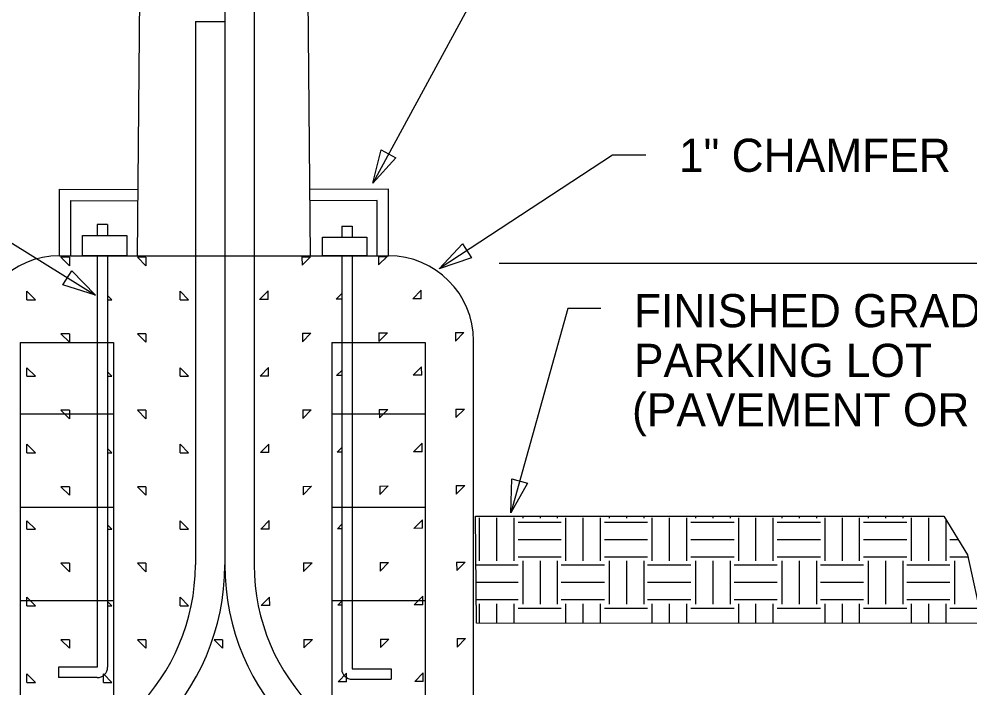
# Model space of a CAD drawing. Extents: x 10117 to 10169, y 10050 to 10161.
# Drawn here: x 10139.75 to 10158.87, y 10084.35 to 10097.81 of the extents above; entities that cross this region are included whole.
import ezdxf

# ---------------------------------------------------------------- set-up
doc = ezdxf.new("R2010")
doc.units = 0
for name, color, linetype in [('G-ANNO-TEXT', 7, 'Continuous'), ('G-DETL-LINE', 7, 'Continuous'), ('G-DETL-OTLN', 7, 'Continuous'), ('G-DETL-PATT', 7, 'Continuous')]:
    doc.layers.add(name, color=color, linetype=linetype)

msp = doc.modelspace()

# ---------------------------------------------------------------- linework, layer by layer
at = {"layer": 'G-ANNO-TEXT'}
for p, q in [((10151.658, 10103.375), (10146.864, 10094.509)), ((10133.842, 10096.882), (10141.285, 10092.251)), ((10151.686, 10095.069), (10148.199, 10092.781)), ((10152.353, 10095.069), (10151.686, 10095.069)), ((10149.402, 10092.896), (10166.935, 10092.896)), ((10150.783, 10091.983), (10149.637, 10087.871)), ((10151.45, 10091.983), (10150.783, 10091.983))]:
    msp.add_line(p, q, dxfattribs=at)
for points in [[(10147.327, 10095.017), (10146.864, 10094.509), (10147.034, 10095.175)], [(10148.848, 10093.007), (10148.199, 10092.781), (10148.665, 10093.286)], [(10140.807, 10092.745), (10141.285, 10092.251), (10140.631, 10092.462)], [(10149.977, 10088.468), (10149.637, 10087.871), (10149.656, 10088.558)]]:
    msp.add_lwpolyline(points, close=True, dxfattribs=at)
at = {"layer": 'G-DETL-LINE'}
for p, q in [((10140.561, 10093.045), (10147.178, 10093.045)), ((10139.772, 10091.302), (10141.65, 10091.302)), ((10139.772, 10091.302), (10139.772, 10082.761)), ((10141.65, 10091.302), (10141.65, 10083.539)), ((10146.039, 10091.302), (10147.916, 10091.302)), ((10146.039, 10091.302), (10146.039, 10083.602)), ((10147.916, 10091.302), (10147.916, 10082.773)), ((10148.889, 10082.719), (10148.889, 10091.334)), ((10139.772, 10089.867), (10141.65, 10089.867)), ((10146.039, 10089.867), (10147.916, 10089.867)), ((10139.772, 10087.989), (10141.65, 10087.989)), ((10146.039, 10087.989), (10147.916, 10087.989)), ((10148.946, 10085.652), (10148.929, 10087.808)), ((10148.929, 10087.808), (10158.347, 10087.808)), ((10158.347, 10087.808), (10158.827, 10087.027)), ((10158.827, 10087.027), (10159.127, 10085.647)), ((10139.772, 10086.111), (10141.65, 10086.111)), ((10146.039, 10086.111), (10147.916, 10086.111)), ((10159.127, 10085.647), (10148.946, 10085.652))]:
    msp.add_line(p, q, dxfattribs=at)
for centre, start, end in [((10140.561, 10091.334), 90, 180), ((10147.178, 10091.334), 360, 90)]:
    msp.add_arc(centre, 1.711, start, end, dxfattribs=at)
at = {"layer": 'G-DETL-OTLN'}
for p, q in [((10142.13, 10093.045), (10142.301, 10113.1)), ((10145.609, 10093.045), (10145.508, 10104.939)), ((10143.885, 10099.179), (10143.885, 10086.825)), ((10144.477, 10099.179), (10144.477, 10086.825)), ((10143.294, 10097.763), (10143.885, 10097.763)), ((10143.294, 10097.763), (10143.294, 10086.825)), ((10140.561, 10094.386), (10142.141, 10094.377)), ((10140.561, 10093.045), (10140.561, 10094.386)), ((10147.178, 10094.386), (10145.598, 10094.377)), ((10147.178, 10093.045), (10147.178, 10094.386)), ((10140.789, 10093.045), (10140.789, 10094.156)), ((10140.789, 10094.156), (10142.139, 10094.149)), ((10146.95, 10094.156), (10145.6, 10094.149)), ((10146.95, 10093.045), (10146.95, 10094.156)), ((10141.32, 10093.676), (10141.32, 10093.452)), ((10141.529, 10093.676), (10141.32, 10093.676)), ((10141.529, 10093.676), (10141.529, 10093.452)), ((10146.239, 10093.641), (10146.448, 10093.641)), ((10146.239, 10093.641), (10146.239, 10093.418)), ((10146.448, 10093.641), (10146.448, 10093.418)), ((10141.32, 10093.045), (10141.32, 10084.765)), ((10141.529, 10093.045), (10141.529, 10084.765)), ((10146.239, 10093.045), (10146.239, 10084.731)), ((10146.448, 10093.045), (10146.448, 10084.731)), ((10141.32, 10084.765), (10140.538, 10084.765)), ((10140.538, 10084.765), (10140.538, 10084.557)), ((10146.448, 10084.731), (10147.23, 10084.731)), ((10147.23, 10084.731), (10147.23, 10084.522)), ((10141.32, 10084.557), (10140.538, 10084.557)), ((10146.448, 10084.522), (10147.23, 10084.522))]:
    msp.add_line(p, q, dxfattribs=at)
for points in [[(10141.022, 10093.452), (10141.916, 10093.452), (10141.916, 10093.045), (10141.022, 10093.045)], [(10145.852, 10093.418), (10146.746, 10093.418), (10146.746, 10093.045), (10145.852, 10093.045)]]:
    msp.add_lwpolyline(points, close=True, dxfattribs=at)
for centre, radius, start, end in [((10139.187, 10086.825), 4.698, 270, 0), ((10139.187, 10086.825), 4.107, 270, 0), ((10148.584, 10086.825), 4.698, 180, 270), ((10148.584, 10086.825), 4.107, 180, 270), ((10141.32, 10084.765), 0.209, 270, 0), ((10146.448, 10084.731), 0.209, 180, 270)]:
    msp.add_arc(centre, radius, start, end, dxfattribs=at)
at = {"layer": 'G-DETL-PATT'}
for p, q in [((10145.438, 10093.025), (10145.609, 10093.026)), ((10145.438, 10093.025), (10145.439, 10092.854)), ((10145.439, 10092.854), (10145.609, 10093.026)), ((10146.978, 10093.033), (10147.149, 10093.033)), ((10146.978, 10093.033), (10146.979, 10092.861)), ((10146.979, 10092.861), (10147.149, 10093.033)), ((10140.761, 10093.017), (10140.59, 10093.017)), ((10140.761, 10092.846), (10140.59, 10093.017)), ((10140.62, 10092.957), (10140.62, 10092.957)), ((10140.761, 10093.017), (10140.761, 10092.846)), ((10142.301, 10093.017), (10142.13, 10093.017)), ((10142.301, 10092.846), (10142.13, 10093.017)), ((10142.301, 10093.017), (10142.301, 10092.846)), ((10147.12, 10092.973), (10147.12, 10092.973)), ((10139.905, 10092.161), (10139.905, 10092.332)), ((10140.076, 10092.161), (10139.905, 10092.332)), ((10142.985, 10092.161), (10142.985, 10092.332)), ((10143.157, 10092.161), (10142.985, 10092.332)), ((10144.587, 10092.165), (10144.757, 10092.337)), ((10144.734, 10092.324), (10144.734, 10092.324)), ((10144.758, 10092.166), (10144.757, 10092.337)), ((10146.127, 10092.173), (10146.239, 10092.286)), ((10147.667, 10092.18), (10147.837, 10092.352)), ((10147.838, 10092.181), (10147.837, 10092.352)), ((10139.905, 10092.161), (10140.076, 10092.161)), ((10141.616, 10092.161), (10141.529, 10092.249)), ((10141.529, 10092.161), (10141.617, 10092.161)), ((10142.985, 10092.161), (10143.157, 10092.161)), ((10144.758, 10092.166), (10144.587, 10092.165)), ((10146.239, 10092.173), (10146.127, 10092.173)), ((10147.838, 10092.181), (10147.667, 10092.18)), ((10146.986, 10091.493), (10147.157, 10091.493)), ((10146.986, 10091.493), (10146.987, 10091.321)), ((10146.987, 10091.321), (10147.157, 10091.493)), ((10148.526, 10091.5), (10148.697, 10091.501)), ((10148.526, 10091.5), (10148.527, 10091.329)), ((10148.527, 10091.329), (10148.697, 10091.501)), ((10140.761, 10091.477), (10140.59, 10091.477)), ((10140.761, 10091.306), (10140.59, 10091.477)), ((10140.761, 10091.477), (10140.761, 10091.306)), ((10142.301, 10091.477), (10142.13, 10091.477)), ((10142.301, 10091.306), (10142.13, 10091.477)), ((10142.301, 10091.477), (10142.301, 10091.306)), ((10145.446, 10091.485), (10145.617, 10091.486)), ((10145.446, 10091.485), (10145.447, 10091.314)), ((10145.447, 10091.314), (10145.617, 10091.486)), ((10139.905, 10090.621), (10139.905, 10090.792)), ((10140.076, 10090.621), (10139.905, 10090.792)), ((10142.985, 10090.621), (10142.985, 10090.792)), ((10143.157, 10090.621), (10142.985, 10090.792)), ((10144.595, 10090.625), (10144.765, 10090.797)), ((10144.766, 10090.626), (10144.765, 10090.797)), ((10146.135, 10090.633), (10146.239, 10090.738)), ((10147.675, 10090.64), (10147.845, 10090.812)), ((10147.846, 10090.641), (10147.845, 10090.812)), ((10139.905, 10090.621), (10140.076, 10090.621)), ((10141.616, 10090.621), (10141.529, 10090.709)), ((10141.529, 10090.621), (10141.617, 10090.621)), ((10142.985, 10090.621), (10143.157, 10090.621)), ((10144.766, 10090.626), (10144.595, 10090.625)), ((10146.239, 10090.633), (10146.135, 10090.633)), ((10147.846, 10090.641), (10147.675, 10090.64)), ((10140.761, 10089.937), (10140.59, 10089.937)), ((10140.761, 10089.766), (10140.59, 10089.937)), ((10140.761, 10089.937), (10140.761, 10089.766)), ((10142.301, 10089.937), (10142.13, 10089.937)), ((10142.301, 10089.766), (10142.13, 10089.937)), ((10142.301, 10089.937), (10142.301, 10089.766)), ((10145.454, 10089.945), (10145.625, 10089.946)), ((10145.454, 10089.945), (10145.455, 10089.774)), ((10145.455, 10089.774), (10145.625, 10089.946)), ((10146.994, 10089.953), (10147.165, 10089.953)), ((10146.994, 10089.953), (10146.995, 10089.781)), ((10146.995, 10089.781), (10147.165, 10089.953)), ((10148.534, 10089.96), (10148.705, 10089.961)), ((10148.534, 10089.96), (10148.535, 10089.789)), ((10148.535, 10089.789), (10148.705, 10089.961)), ((10148.567, 10089.832), (10148.567, 10089.832)), ((10139.905, 10089.081), (10139.905, 10089.252)), ((10140.076, 10089.081), (10139.905, 10089.252)), ((10142.985, 10089.081), (10142.985, 10089.252)), ((10143.157, 10089.081), (10142.985, 10089.252)), ((10144.603, 10089.085), (10144.773, 10089.257)), ((10144.774, 10089.086), (10144.773, 10089.257)), ((10147.683, 10089.1), (10147.853, 10089.272)), ((10147.854, 10089.101), (10147.853, 10089.272)), ((10139.905, 10089.081), (10140.076, 10089.081)), ((10141.616, 10089.081), (10141.529, 10089.169)), ((10141.529, 10089.081), (10141.617, 10089.081)), ((10142.985, 10089.081), (10143.157, 10089.081)), ((10144.774, 10089.086), (10144.602, 10089.085)), ((10146.143, 10089.093), (10146.239, 10089.19)), ((10146.239, 10089.093), (10146.143, 10089.093)), ((10147.854, 10089.101), (10147.683, 10089.1)), ((10140.761, 10088.397), (10140.59, 10088.397)), ((10140.761, 10088.226), (10140.59, 10088.397)), ((10140.761, 10088.397), (10140.761, 10088.226)), ((10142.301, 10088.397), (10142.13, 10088.397)), ((10142.301, 10088.226), (10142.13, 10088.397)), ((10142.301, 10088.397), (10142.301, 10088.226)), ((10145.461, 10088.405), (10145.633, 10088.406)), ((10145.461, 10088.405), (10145.462, 10088.234)), ((10145.462, 10088.234), (10145.633, 10088.406)), ((10147.002, 10088.412), (10147.173, 10088.413)), ((10147.002, 10088.241), (10147.173, 10088.413)), ((10147.002, 10088.412), (10147.002, 10088.241)), ((10148.542, 10088.42), (10148.713, 10088.421)), ((10148.542, 10088.249), (10148.713, 10088.421)), ((10148.542, 10088.42), (10148.542, 10088.249)), ((10148.644, 10088.345), (10148.644, 10088.345)), ((10139.905, 10087.541), (10139.905, 10087.712)), ((10140.076, 10087.541), (10139.905, 10087.712)), ((10142.985, 10087.541), (10142.985, 10087.712)), ((10143.157, 10087.541), (10142.985, 10087.712)), ((10144.61, 10087.545), (10144.781, 10087.717)), ((10144.781, 10087.546), (10144.78, 10087.717)), ((10147.69, 10087.56), (10147.861, 10087.732)), ((10147.861, 10087.561), (10147.861, 10087.732)), ((10149.003, 10087.772), (10149.003, 10086.903)), ((10149.351, 10087.772), (10149.351, 10086.903)), ((10149.698, 10087.772), (10149.698, 10086.903)), ((10149.785, 10087.685), (10150.654, 10087.685)), ((10149.878, 10087.808), (10149.878, 10087.766)), ((10150.226, 10087.808), (10150.226, 10087.766)), ((10150.573, 10087.808), (10150.573, 10087.766)), ((10150.741, 10087.772), (10150.741, 10086.903)), ((10151.088, 10087.772), (10151.088, 10086.903)), ((10151.436, 10087.772), (10151.436, 10086.903)), ((10151.522, 10087.685), (10152.391, 10087.685)), ((10151.616, 10087.808), (10151.616, 10087.766)), ((10151.963, 10087.808), (10151.963, 10087.766)), ((10152.311, 10087.808), (10152.311, 10087.766)), ((10152.478, 10087.772), (10152.478, 10086.903)), ((10152.825, 10087.772), (10152.825, 10086.903)), ((10153.173, 10087.772), (10153.173, 10086.903)), ((10153.26, 10087.685), (10154.128, 10087.685)), ((10153.353, 10087.808), (10153.353, 10087.766)), ((10153.701, 10087.808), (10153.701, 10087.766)), ((10154.048, 10087.808), (10154.048, 10087.766)), ((10154.215, 10087.772), (10154.215, 10086.903)), ((10154.563, 10087.772), (10154.563, 10086.903)), ((10154.91, 10087.772), (10154.91, 10086.903)), ((10154.997, 10087.685), (10155.866, 10087.685)), ((10155.09, 10087.808), (10155.09, 10087.766)), ((10155.438, 10087.808), (10155.438, 10087.766)), ((10155.785, 10087.808), (10155.785, 10087.766)), ((10155.953, 10087.772), (10155.953, 10086.903)), ((10156.3, 10087.772), (10156.3, 10086.903)), ((10156.648, 10087.772), (10156.648, 10086.903)), ((10156.734, 10087.685), (10157.603, 10087.685)), ((10156.828, 10087.808), (10156.828, 10087.766)), ((10157.175, 10087.808), (10157.175, 10087.766)), ((10157.523, 10087.808), (10157.523, 10087.766)), ((10157.69, 10087.772), (10157.69, 10086.903)), ((10158.037, 10087.772), (10158.037, 10086.903)), ((10158.385, 10087.747), (10158.385, 10086.903)), ((10139.905, 10087.541), (10140.076, 10087.541)), ((10141.616, 10087.541), (10141.529, 10087.629)), ((10141.529, 10087.541), (10141.617, 10087.541)), ((10142.985, 10087.541), (10143.157, 10087.541)), ((10144.781, 10087.546), (10144.61, 10087.545)), ((10146.15, 10087.553), (10146.239, 10087.643)), ((10146.239, 10087.553), (10146.15, 10087.553)), ((10147.861, 10087.561), (10147.69, 10087.56)), ((10149.785, 10087.338), (10150.654, 10087.338)), ((10151.522, 10087.338), (10152.391, 10087.338)), ((10153.26, 10087.338), (10154.128, 10087.338)), ((10154.997, 10087.338), (10155.866, 10087.338)), ((10156.734, 10087.338), (10157.603, 10087.338)), ((10158.472, 10087.338), (10158.636, 10087.338)), ((10149.785, 10086.99), (10150.654, 10086.99)), ((10149.878, 10086.903), (10149.878, 10086.035)), ((10150.226, 10086.903), (10150.226, 10086.035)), ((10150.573, 10086.903), (10150.573, 10086.035)), ((10151.522, 10086.99), (10152.391, 10086.99)), ((10151.616, 10086.903), (10151.616, 10086.035)), ((10151.963, 10086.903), (10151.963, 10086.035)), ((10152.311, 10086.903), (10152.311, 10086.035)), ((10153.26, 10086.99), (10154.128, 10086.99)), ((10153.353, 10086.903), (10153.353, 10086.035)), ((10153.701, 10086.903), (10153.701, 10086.035)), ((10154.048, 10086.903), (10154.048, 10086.035)), ((10154.997, 10086.99), (10155.866, 10086.99)), ((10155.09, 10086.903), (10155.09, 10086.035)), ((10155.438, 10086.903), (10155.438, 10086.035)), ((10155.785, 10086.903), (10155.785, 10086.035)), ((10156.734, 10086.99), (10157.603, 10086.99)), ((10156.828, 10086.903), (10156.828, 10086.035)), ((10157.175, 10086.903), (10157.175, 10086.035)), ((10157.523, 10086.903), (10157.523, 10086.035)), ((10158.472, 10086.99), (10158.835, 10086.99)), ((10158.565, 10086.903), (10158.565, 10086.035)), ((10140.761, 10086.857), (10140.59, 10086.857)), ((10140.761, 10086.686), (10140.59, 10086.857)), ((10140.761, 10086.857), (10140.761, 10086.686)), ((10142.301, 10086.857), (10142.13, 10086.857)), ((10142.301, 10086.686), (10142.13, 10086.857)), ((10142.301, 10086.857), (10142.301, 10086.686)), ((10145.469, 10086.865), (10145.64, 10086.866)), ((10145.469, 10086.865), (10145.47, 10086.694)), ((10145.47, 10086.694), (10145.64, 10086.866)), ((10147.009, 10086.872), (10147.18, 10086.873)), ((10147.009, 10086.872), (10147.01, 10086.701)), ((10147.01, 10086.701), (10147.18, 10086.873)), ((10148.549, 10086.88), (10148.72, 10086.881)), ((10148.549, 10086.88), (10148.55, 10086.709)), ((10148.55, 10086.709), (10148.72, 10086.881)), ((10148.936, 10086.823), (10149.785, 10086.823)), ((10150.654, 10086.823), (10151.522, 10086.823)), ((10152.391, 10086.823), (10153.26, 10086.823)), ((10154.128, 10086.823), (10154.997, 10086.823)), ((10155.866, 10086.823), (10156.734, 10086.823)), ((10157.603, 10086.823), (10158.472, 10086.823)), ((10148.939, 10086.475), (10149.785, 10086.475)), ((10150.654, 10086.475), (10151.522, 10086.475)), ((10152.391, 10086.475), (10153.26, 10086.475)), ((10154.128, 10086.475), (10154.997, 10086.475)), ((10155.866, 10086.475), (10156.734, 10086.475)), ((10157.603, 10086.475), (10158.472, 10086.475)), ((10139.905, 10086.001), (10139.905, 10086.172)), ((10140.076, 10086.001), (10139.905, 10086.172)), ((10142.985, 10086.001), (10142.985, 10086.172)), ((10143.157, 10086.001), (10142.985, 10086.172)), ((10144.618, 10086.005), (10144.788, 10086.177)), ((10144.789, 10086.006), (10144.788, 10086.177)), ((10147.698, 10086.02), (10147.868, 10086.192)), ((10147.869, 10086.021), (10147.868, 10086.192)), ((10139.905, 10086.001), (10140.076, 10086.001)), ((10141.616, 10086.001), (10141.529, 10086.089)), ((10141.529, 10086.001), (10141.617, 10086.001)), ((10142.985, 10086.001), (10143.157, 10086.001)), ((10144.789, 10086.006), (10144.618, 10086.005)), ((10146.158, 10086.013), (10146.239, 10086.095)), ((10146.239, 10086.013), (10146.158, 10086.013)), ((10147.869, 10086.021), (10147.698, 10086.02)), ((10148.942, 10086.128), (10149.785, 10086.128)), ((10149.003, 10086.041), (10149.003, 10085.652)), ((10149.351, 10086.041), (10149.351, 10085.652)), ((10149.698, 10086.041), (10149.698, 10085.652)), ((10149.785, 10085.954), (10150.654, 10085.954)), ((10150.654, 10086.128), (10151.522, 10086.128)), ((10150.741, 10086.041), (10150.741, 10085.651)), ((10151.088, 10086.041), (10151.088, 10085.651)), ((10151.436, 10086.041), (10151.436, 10085.651)), ((10151.522, 10085.954), (10152.391, 10085.954)), ((10152.391, 10086.128), (10153.26, 10086.128)), ((10152.478, 10086.041), (10152.478, 10085.65)), ((10152.825, 10086.041), (10152.825, 10085.65)), ((10153.173, 10086.041), (10153.173, 10085.65)), ((10153.26, 10085.954), (10154.128, 10085.954)), ((10154.128, 10086.128), (10154.997, 10086.128)), ((10154.215, 10086.041), (10154.215, 10085.649)), ((10154.563, 10086.041), (10154.563, 10085.649)), ((10154.91, 10086.041), (10154.91, 10085.649)), ((10154.997, 10085.954), (10155.866, 10085.954)), ((10155.866, 10086.128), (10156.734, 10086.128)), ((10155.953, 10086.041), (10155.953, 10085.649)), ((10156.3, 10086.041), (10156.3, 10085.648)), ((10156.648, 10086.041), (10156.648, 10085.648)), ((10156.734, 10085.954), (10157.603, 10085.954)), ((10157.603, 10086.128), (10158.472, 10086.128)), ((10157.69, 10086.041), (10157.69, 10085.648)), ((10158.037, 10086.041), (10158.037, 10085.647)), ((10158.385, 10086.041), (10158.385, 10085.647)), ((10158.472, 10085.954), (10159.061, 10085.954)), ((10140.761, 10085.317), (10140.59, 10085.317)), ((10140.761, 10085.146), (10140.59, 10085.317)), ((10140.761, 10085.317), (10140.761, 10085.146)), ((10142.301, 10085.317), (10142.13, 10085.317)), ((10142.301, 10085.146), (10142.13, 10085.317)), ((10142.301, 10085.317), (10142.301, 10085.146)), ((10143.841, 10085.317), (10143.67, 10085.317)), ((10143.841, 10085.146), (10143.67, 10085.317)), ((10143.841, 10085.317), (10143.841, 10085.146)), ((10145.477, 10085.325), (10145.648, 10085.326)), ((10145.477, 10085.325), (10145.478, 10085.154)), ((10145.478, 10085.154), (10145.648, 10085.326)), ((10147.017, 10085.332), (10147.188, 10085.333)), ((10147.017, 10085.332), (10147.018, 10085.161)), ((10147.018, 10085.161), (10147.188, 10085.333)), ((10148.557, 10085.34), (10148.728, 10085.341)), ((10148.557, 10085.34), (10148.558, 10085.169)), ((10148.558, 10085.169), (10148.728, 10085.341)), ((10139.905, 10084.461), (10139.905, 10084.632)), ((10140.076, 10084.461), (10139.905, 10084.632)), ((10141.445, 10084.461), (10141.445, 10084.632)), ((10141.616, 10084.461), (10141.445, 10084.632)), ((10146.166, 10084.473), (10146.336, 10084.644)), ((10146.337, 10084.473), (10146.336, 10084.644)), ((10147.706, 10084.48), (10147.876, 10084.652)), ((10147.877, 10084.481), (10147.876, 10084.652)), ((10139.905, 10084.461), (10140.076, 10084.461)), ((10141.445, 10084.461), (10141.617, 10084.461)), ((10146.337, 10084.473), (10146.166, 10084.473)), ((10147.877, 10084.481), (10147.706, 10084.48))]:
    msp.add_line(p, q, dxfattribs=at)

# ---------------------------------------------------------------- texts
at = {"layer": 'G-ANNO-TEXT'}
for s, height, p in [('1" CHAMFER', 0.6667, (10153.02, 10094.735)), ('FINISHED GRADE OF ', 0.66667, (10152.116, 10091.608)), ('PARKING LOT', 0.66667, (10152.116, 10090.608)), ('(PAVEMENT OR LAWN)', 0.66667, (10152.077, 10089.614))]:
    msp.add_text(s, height=height, dxfattribs=at).set_placement(p)

doc.saveas('drawing.dxf')
